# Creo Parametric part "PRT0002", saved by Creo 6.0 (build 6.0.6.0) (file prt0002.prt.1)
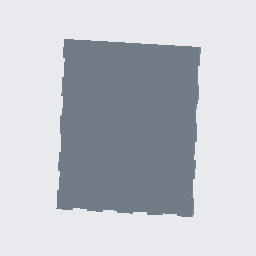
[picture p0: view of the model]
Units: Inch lbm Second (Pro/E Default); INCH, POUND, SECS

Created from: INLBS_PART_SOLID.PRT

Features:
  1. datum plane "RIGHT"
  2. datum plane "TOP"
  3. datum plane "FRONT"
  4. coordinate system
  5. sketch "Sketch 1"
  6. extrusion "Extrude 1"

Surfaces: 54 plane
